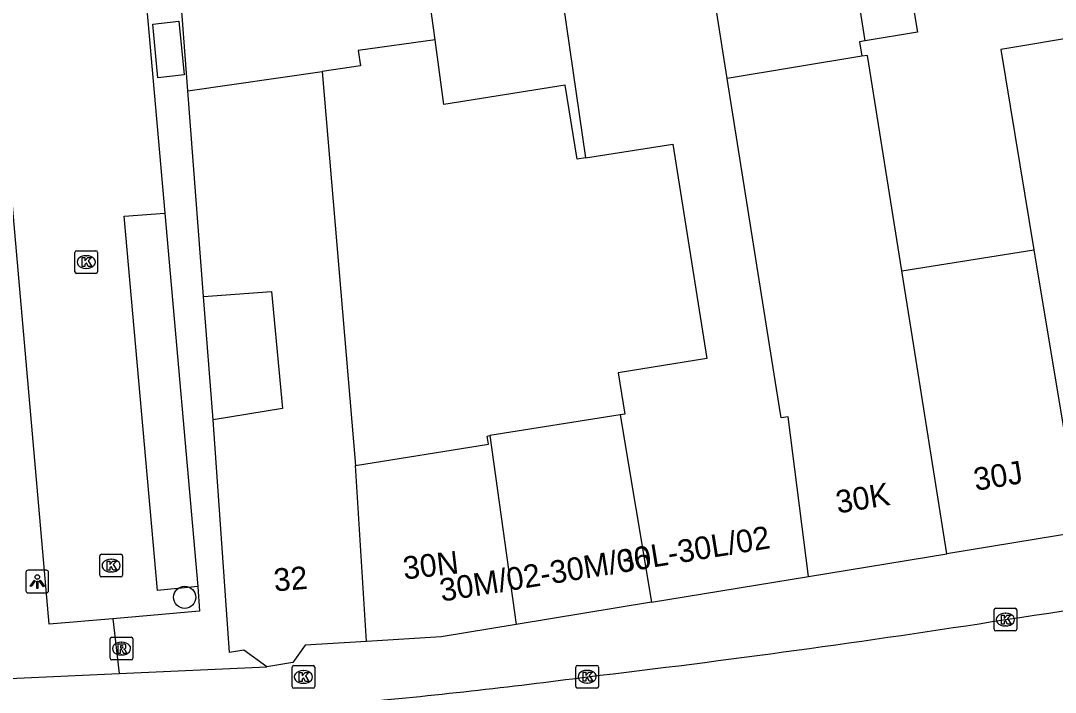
# Model space of a CAD drawing. Extents: x 160026 to 161302, y 384757 to 385701.
# Drawn here: x 160600.37 to 160645.83, y 384817.61 to 384847.14 of the extents above; entities that cross this region are included whole.
import ezdxf

# ---------------------------------------------------------------- set-up
doc = ezdxf.new("R2010")
doc.units = 0
for name, color, linetype in [('IMGEO_Boom', 7, 'Continuous'), ('IMGEO_Kolk', 7, 'Continuous'), ('IMGEO_Lichtpunt', 7, 'Continuous'), ('IMGEO_Muur', 7, 'Continuous'), ('IMGEO_Pand', 7, 'Continuous'), ('IMGEO_Pand_nummerreeks', 7, 'Continuous'), ('IMGEO_Rijbaan_lokaal_open', 7, 'Continuous'), ('IMGEO_Rioolput', 7, 'Continuous'), ('IMGEO_Voetpad_gesloten', 7, 'Continuous'), ('IMGEO_Voetpad_open', 7, 'Continuous')]:
    doc.layers.add(name, color=color, linetype=linetype)

msp = doc.modelspace()

# ---------------------------------------------------------------- linework, layer by layer
at = {"layer": 'IMGEO_Boom'}
msp.add_circle((160607.574, 384821.784), 0.489, dxfattribs=at)
at = {"layer": 'IMGEO_Kolk'}
for p, q in [((160602.819, 384837.025), (160603.671, 384837.025)), ((160602.744, 384836.099), (160602.744, 384836.951)), ((160603.232, 384836.805), (160603.257, 384836.805)), ((160603.745, 384836.951), (160603.745, 384836.099)), ((160603.255, 384836.245), (160603.23, 384836.245)), ((160603.671, 384836.025), (160602.819, 384836.025)), ((160603.839, 384822.754), (160603.839, 384823.606)), ((160603.914, 384823.68), (160604.766, 384823.68)), ((160604.327, 384823.46), (160604.352, 384823.46)), ((160604.84, 384823.606), (160604.84, 384822.754)), ((160604.35, 384822.9), (160604.325, 384822.9)), ((160604.766, 384822.68), (160603.914, 384822.68)), ((160643.142, 384820.379), (160643.142, 384821.231)), ((160643.217, 384821.305), (160644.069, 384821.305)), ((160643.63, 384821.085), (160643.655, 384821.085)), ((160644.143, 384821.231), (160644.143, 384820.379)), ((160644.069, 384820.305), (160643.217, 384820.305)), ((160643.653, 384820.525), (160643.628, 384820.525)), ((160612.29, 384817.857), (160612.29, 384818.709)), ((160612.365, 384818.783), (160613.217, 384818.783)), ((160612.778, 384818.563), (160612.803, 384818.563)), ((160613.291, 384818.709), (160613.291, 384817.857)), ((160624.76, 384817.864), (160624.76, 384818.716)), ((160624.835, 384818.79), (160625.687, 384818.79)), ((160625.248, 384818.57), (160625.273, 384818.57)), ((160625.761, 384818.716), (160625.761, 384817.864)), ((160612.801, 384818.003), (160612.776, 384818.003)), ((160625.271, 384818.01), (160625.246, 384818.01)), ((160613.217, 384817.783), (160612.365, 384817.783)), ((160625.687, 384817.79), (160624.835, 384817.79))]:
    msp.add_line(p, q, dxfattribs=at)
for points in [[(160602.819, 384837.025), (160603.671, 384837.025)], [(160602.744, 384836.099), (160602.744, 384836.951)], [(160603.065, 384836.725), (160603.188, 384836.725), (160603.188, 384836.574), (160603.318, 384836.725), (160603.482, 384836.725), (160603.336, 384836.574), (160603.489, 384836.325), (160603.337, 384836.325), (160603.252, 384836.489), (160603.188, 384836.422), (160603.188, 384836.325), (160603.065, 384836.325), (160603.065, 384836.725)], [(160603.745, 384836.951), (160603.745, 384836.099)], [(160603.671, 384836.025), (160602.819, 384836.025)], [(160603.839, 384822.754), (160603.839, 384823.606)], [(160603.914, 384823.68), (160604.766, 384823.68)], [(160604.16, 384823.38), (160604.283, 384823.38), (160604.283, 384823.229), (160604.413, 384823.38), (160604.577, 384823.38), (160604.431, 384823.229), (160604.584, 384822.98), (160604.432, 384822.98), (160604.347, 384823.144), (160604.283, 384823.077), (160604.283, 384822.98), (160604.16, 384822.98), (160604.16, 384823.38)], [(160604.84, 384823.606), (160604.84, 384822.754)], [(160604.766, 384822.68), (160603.914, 384822.68)], [(160643.142, 384820.379), (160643.142, 384821.231)], [(160643.217, 384821.305), (160644.069, 384821.305)], [(160644.143, 384821.231), (160644.143, 384820.379)], [(160643.463, 384821.005), (160643.586, 384821.005), (160643.586, 384820.854), (160643.716, 384821.005), (160643.88, 384821.005), (160643.734, 384820.854), (160643.887, 384820.605), (160643.735, 384820.605), (160643.65, 384820.769), (160643.586, 384820.702), (160643.586, 384820.605), (160643.463, 384820.605), (160643.463, 384821.005)], [(160644.069, 384820.305), (160643.217, 384820.305)], [(160612.29, 384817.857), (160612.29, 384818.709)], [(160612.365, 384818.783), (160613.217, 384818.783)], [(160612.611, 384818.483), (160612.734, 384818.483), (160612.734, 384818.332), (160612.864, 384818.483), (160613.028, 384818.483), (160612.882, 384818.332), (160613.035, 384818.083), (160612.883, 384818.083), (160612.798, 384818.247), (160612.734, 384818.18), (160612.734, 384818.083), (160612.611, 384818.083), (160612.611, 384818.483)], [(160613.291, 384818.709), (160613.291, 384817.857)], [(160624.76, 384817.864), (160624.76, 384818.716)], [(160624.835, 384818.79), (160625.687, 384818.79)], [(160625.081, 384818.49), (160625.204, 384818.49), (160625.204, 384818.339), (160625.334, 384818.49), (160625.498, 384818.49), (160625.352, 384818.339), (160625.505, 384818.09), (160625.353, 384818.09), (160625.268, 384818.254), (160625.204, 384818.187), (160625.204, 384818.09), (160625.081, 384818.09), (160625.081, 384818.49)], [(160625.761, 384818.716), (160625.761, 384817.864)], [(160613.217, 384817.783), (160612.365, 384817.783)], [(160625.687, 384817.79), (160624.835, 384817.79)]]:
    msp.add_lwpolyline(points, dxfattribs=at)
for centre, start, end in [((160602.821, 384836.949), 91.552, 178.448), ((160602.821, 384836.949), 91.552, 178.448), ((160603.669, 384836.949), 1.552, 88.448), ((160603.669, 384836.949), 1.552, 88.448), ((160602.821, 384836.101), 181.552, 268.448), ((160602.821, 384836.101), 181.552, 268.448), ((160603.669, 384836.101), 271.552, 358.448), ((160603.669, 384836.101), 271.552, 358.448), ((160603.916, 384823.604), 91.552, 178.448), ((160603.916, 384823.604), 91.552, 178.448), ((160604.764, 384823.604), 1.552, 88.448), ((160604.764, 384823.604), 1.552, 88.448), ((160603.916, 384822.756), 181.552, 268.448), ((160603.916, 384822.756), 181.552, 268.448), ((160604.764, 384822.756), 271.552, 358.448), ((160604.764, 384822.756), 271.552, 358.448), ((160643.219, 384821.229), 91.552, 178.448), ((160643.219, 384821.229), 91.552, 178.448), ((160644.067, 384821.229), 1.552, 88.448), ((160644.067, 384821.229), 1.552, 88.448), ((160643.219, 384820.381), 181.552, 268.448), ((160643.219, 384820.381), 181.552, 268.448), ((160644.067, 384820.381), 271.552, 358.448), ((160644.067, 384820.381), 271.552, 358.448), ((160612.367, 384818.707), 91.552, 178.448), ((160612.367, 384818.707), 91.552, 178.448), ((160613.215, 384818.707), 1.552, 88.448), ((160613.215, 384818.707), 1.552, 88.448), ((160624.837, 384818.714), 91.552, 178.448), ((160624.837, 384818.714), 91.552, 178.448), ((160625.685, 384818.714), 1.552, 88.448), ((160625.685, 384818.714), 1.552, 88.448), ((160612.367, 384817.859), 181.552, 268.448), ((160612.367, 384817.859), 181.552, 268.448), ((160613.215, 384817.859), 271.552, 358.448), ((160613.215, 384817.859), 271.552, 358.448), ((160624.837, 384817.866), 181.552, 268.448), ((160624.837, 384817.866), 181.552, 268.448), ((160625.685, 384817.866), 271.552, 358.448), ((160625.685, 384817.866), 271.552, 358.448)]:
    msp.add_arc(centre, 0.0765, start, end, dxfattribs=at)
for centre, major_axis, ratio, start_param, end_param in [((160603.231, 384836.525), (-0.387, 0.002), 0.722429, 4.712389, 7.853982), ((160603.256, 384836.525), (-0.39, 0.002), 0.717154, 1.570796, 4.712389), ((160604.326, 384823.18), (-0.387, 0.002), 0.722429, 4.712389, 7.853982), ((160604.351, 384823.18), (-0.39, 0.002), 0.717154, 1.570796, 4.712389), ((160643.629, 384820.805), (-0.387, 0.002), 0.722429, 4.712389, 7.853982), ((160643.654, 384820.805), (-0.39, 0.002), 0.717154, 1.570796, 4.712389), ((160612.777, 384818.283), (-0.387, 0.002), 0.722429, 4.712389, 7.853982), ((160612.802, 384818.283), (-0.39, 0.002), 0.717154, 1.570796, 4.712389), ((160625.247, 384818.29), (-0.387, 0.002), 0.722429, 4.712389, 7.853982), ((160625.272, 384818.29), (-0.39, 0.002), 0.717154, 1.570796, 4.712389)]:
    msp.add_ellipse(centre, major_axis=major_axis, ratio=ratio, start_param=start_param, end_param=end_param, dxfattribs=at)
at = {"layer": 'IMGEO_Lichtpunt'}
for p, q in [((160601.497, 384822.974), (160600.689, 384822.974)), ((160601.497, 384822.974), (160600.689, 384822.974)), ((160600.595, 384822.879), (160600.595, 384822.072)), ((160600.595, 384822.879), (160600.595, 384822.072)), ((160601.591, 384822.072), (160601.591, 384822.879)), ((160601.591, 384822.072), (160601.591, 384822.879)), ((160600.689, 384821.978), (160601.497, 384821.978)), ((160600.689, 384821.978), (160601.497, 384821.978))]:
    msp.add_line(p, q, dxfattribs=at)
for points in [[(160600.969, 384822.543), (160601.008, 384822.515), (160600.82, 384822.253), (160600.782, 384822.28), (160600.969, 384822.543)], [(160601.071, 384822.495), (160601.118, 384822.495), (160601.118, 384822.173), (160601.071, 384822.173), (160601.071, 384822.495)], [(160601.181, 384822.515), (160601.219, 384822.542), (160601.406, 384822.28), (160601.367, 384822.252), (160601.181, 384822.515)]]:
    msp.add_lwpolyline(points, dxfattribs=at)
msp.add_circle((160601.094, 384822.677), 0.0994, dxfattribs=at)
for centre, start, end in [((160600.689, 384822.879), 90, 180), ((160600.689, 384822.879), 90, 180), ((160601.497, 384822.879), 0, 90), ((160601.497, 384822.879), 0, 90), ((160600.689, 384822.072), 180, 270), ((160600.689, 384822.072), 180, 270), ((160601.497, 384822.072), 270, 0), ((160601.497, 384822.072), 270, 360)]:
    msp.add_arc(centre, 0.0946, start, end, dxfattribs=at)
at = {"layer": 'IMGEO_Muur'}
msp.add_lwpolyline([(160608.823, 384829.581), (160608.396, 384835.005)], dxfattribs=at)
at = {"layer": 'IMGEO_Pand'}
for points in [[(160636.593, 384851.833), (160645.107, 384853.194), (160645.677, 384849.729), (160642.842, 384849.262), (160642.893, 384848.953), (160639.486, 384848.393), (160639.776, 384846.63), (160637.481, 384846.253)], [(160637.481, 384846.253), (160636.593, 384851.833)], [(160631.42, 384844.602), (160630.428, 384850.848)], [(160623.923, 384849.808), (160625.186, 384841.104)], [(160618.575, 384846.299), (160618.136, 384849.475)], [(160607.707, 384844.059), (160607.413, 384847.936)], [(160618.575, 384846.299), (160615.199, 384845.832), (160615.294, 384845.148), (160613.61, 384844.906)], [(160625.186, 384841.104), (160624.817, 384841.045), (160624.299, 384844.305), (160618.968, 384843.459), (160618.575, 384846.299)], [(160637.481, 384846.253), (160637.228, 384846.211), (160637.333, 384845.574)], [(160656.523, 384840.386), (160648.336, 384839.039), (160647.112, 384846.482), (160643.439, 384845.877), (160644.89, 384837.059)], [(160637.333, 384845.574), (160631.42, 384844.602)], [(160639.09, 384836.136), (160637.582, 384845.615), (160637.333, 384845.574)], [(160607.707, 384844.059), (160613.61, 384844.906)], [(160613.61, 384844.906), (160615.085, 384827.586)], [(160634.982, 384822.699), (160634.094, 384829.722), (160633.79, 384829.672), (160633.588, 384830.946), (160631.42, 384844.602)], [(160608.396, 384835.005), (160607.707, 384844.059)], [(160625.186, 384841.104), (160629.021, 384841.712), (160630.518, 384832.279), (160626.619, 384831.66), (160626.909, 384829.833), (160626.711, 384829.802)], [(160639.09, 384836.136), (160644.89, 384837.059)], [(160644.89, 384837.059), (160645.427, 384833.796), (160646.962, 384824.67)], [(160641.068, 384823.701), (160639.614, 384832.84), (160639.09, 384836.136)], [(160608.396, 384835.005), (160611.385, 384835.234), (160611.876, 384830.083), (160608.823, 384829.581)], [(160626.711, 384829.802), (160620.985, 384828.893)], [(160626.711, 384829.802), (160628.087, 384821.565)], [(160611.184, 384818.734), (160610.177, 384819.457), (160609.539, 384819.352), (160608.823, 384829.581)], [(160615.085, 384827.586), (160620.93, 384828.514), (160620.873, 384828.875), (160620.985, 384828.893)], [(160620.985, 384828.893), (160622.135, 384820.586)], [(160615.568, 384819.841), (160615.085, 384827.586)], [(160646.962, 384824.67), (160641.068, 384823.701)], [(160634.982, 384822.699), (160641.068, 384823.701)], [(160628.087, 384821.565), (160634.982, 384822.699)], [(160628.087, 384821.565), (160622.135, 384820.586)], [(160622.135, 384820.586), (160618.838, 384820.044), (160615.568, 384819.841)], [(160615.568, 384819.841), (160612.867, 384819.674), (160612.327, 384818.922), (160611.184, 384818.734)]]:
    msp.add_lwpolyline(points, dxfattribs=at)
at = {"layer": 'IMGEO_Rijbaan_lokaal_open'}
for points in [[(160605.248, 384855.107), (160606.694, 384838.682)], [(160604.414, 384820.845), (160601.61, 384820.597), (160598.909, 384851.411), (160597.394, 384851.417)], [(160608.145, 384822.259), (160606.374, 384822.087), (160604.917, 384838.539), (160606.694, 384838.682)], [(160608.145, 384822.259), (160608.217, 384821.182), (160604.414, 384820.845)]]:
    msp.add_lwpolyline(points, dxfattribs=at)
for centre, radius, start, end in [((160577.531, 385266.345), 450.419, 278.43975, 281.05867), ((160568.808, 385299.496), 484.507, 276.69062, 278.88477), ((160556.367, 385390.208), 581.014, 276.943921, 280.706664), ((160591.646, 385073.025), 256.944, 275.22547, 277.5165)]:
    msp.add_arc(centre, radius, start, end, dxfattribs=at)
at = {"layer": 'IMGEO_Rioolput'}
for p, q in [((160604.295, 384819.104), (160604.295, 384819.956)), ((160604.37, 384820.03), (160605.222, 384820.03)), ((160604.783, 384819.81), (160604.808, 384819.81)), ((160605.296, 384819.956), (160605.296, 384819.104)), ((160605.222, 384819.03), (160604.37, 384819.03)), ((160604.806, 384819.25), (160604.781, 384819.25))]:
    msp.add_line(p, q, dxfattribs=at)
for points in [[(160604.295, 384819.104), (160604.295, 384819.956)], [(160604.37, 384820.03), (160605.222, 384820.03)], [(160604.884, 384819.728), (160604.632, 384819.73), (160604.632, 384819.33)], [(160605.296, 384819.956), (160605.296, 384819.104)], [(160604.632, 384819.33), (160604.756, 384819.33), (160604.756, 384819.492), (160604.767, 384819.492)], [(160604.81, 384819.649), (160604.756, 384819.649), (160604.756, 384819.568)], [(160604.756, 384819.568), (160604.808, 384819.568)], [(160604.814, 384819.463), (160604.885, 384819.33), (160605.025, 384819.33), (160604.96, 384819.456)], [(160605.222, 384819.03), (160604.37, 384819.03)]]:
    msp.add_lwpolyline(points, dxfattribs=at)
for centre, radius, start, end in [((160604.372, 384819.954), 0.0765, 91.552, 178.448), ((160604.372, 384819.954), 0.0765, 91.552, 178.448), ((160604.883, 384819.618), 0.109, 350.3612, 89.416), ((160605.22, 384819.954), 0.0765, 1.552, 88.448), ((160605.22, 384819.954), 0.0765, 1.552, 88.448), ((160604.766, 384819.439), 0.0533, 26.0293, 88.6989), ((160604.792, 384819.757), 0.19, 274.7715, 282.9687), ((160604.816, 384819.553), 0.0964, 77.0061, 93.1865), ((160604.83, 384819.61), 0.0378, 276.6634, 79.6772), ((160604.881, 384819.618), 0.112, 277.5842, 350.9817), ((160604.865, 384819.403), 0.108, 29.5134, 73.7905), ((160604.372, 384819.106), 0.0765, 181.552, 268.448), ((160604.372, 384819.106), 0.0765, 181.552, 268.448), ((160605.22, 384819.106), 0.0765, 271.552, 358.448), ((160605.22, 384819.106), 0.0765, 271.552, 358.448)]:
    msp.add_arc(centre, radius, start, end, dxfattribs=at)
for centre, major_axis, ratio, start_param, end_param in [((160604.782, 384819.53), (-0.387, 0.002), 0.722429, 4.712389, 7.853982), ((160604.807, 384819.53), (-0.39, 0.002), 0.717154, 1.570796, 4.712389)]:
    msp.add_ellipse(centre, major_axis=major_axis, ratio=ratio, start_param=start_param, end_param=end_param, dxfattribs=at)
at = {"layer": 'IMGEO_Voetpad_gesloten'}
msp.add_lwpolyline([(160606.394, 384844.625), (160606.173, 384846.985), (160607.312, 384847.113), (160607.547, 384844.765), (160606.394, 384844.625)], dxfattribs=at)
at = {"layer": 'IMGEO_Voetpad_open'}
for points in [[(160606.694, 384838.682), (160608.145, 384822.259)], [(160608.823, 384829.581), (160608.396, 384835.005)], [(160604.414, 384820.845), (160604.686, 384818.432)], [(160599.877, 384818.208), (160604.686, 384818.432)], [(160604.686, 384818.432), (160611.184, 384818.734)]]:
    msp.add_lwpolyline(points, dxfattribs=at)

# ---------------------------------------------------------------- texts
at = {"layer": 'IMGEO_Pand_nummerreeks'}
for s, rotation, p in [('30J', 9.3392, (160642.333, 384826.463)), ('30K', 9.3392, (160636.274, 384825.466)), ('30L-30L/02', 9.3392, (160626.676, 384822.853)), ('30N', 6.4718, (160617.22, 384822.565)), ('30M/02-30M/06', 9.1444, (160618.867, 384821.591)), ('32', 4.641, (160611.523, 384822.041))]:
    msp.add_text(s, height=1, rotation=rotation, dxfattribs=at).set_placement(p)

doc.saveas('drawing.dxf')
